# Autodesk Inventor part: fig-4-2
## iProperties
Shininess: 64.0
Length Units: 11272
Angle Units: 11279
Time Units: 11290
Mass Units: 11283
Length Display Precision: 3
Angle Display Precision: 2
Compacted: True
Part Number: fig-4-2
Document SubType Name: Modeling
Created: 2003-01
Designer: Owner
Density: 0.0
Volumn: 0.0
Area: 0.0
PropertySet Name: Model Information
Control State: 0
Master: False
Checked Out: False
Author: Owner
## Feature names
1. ExtrusionBlind1
